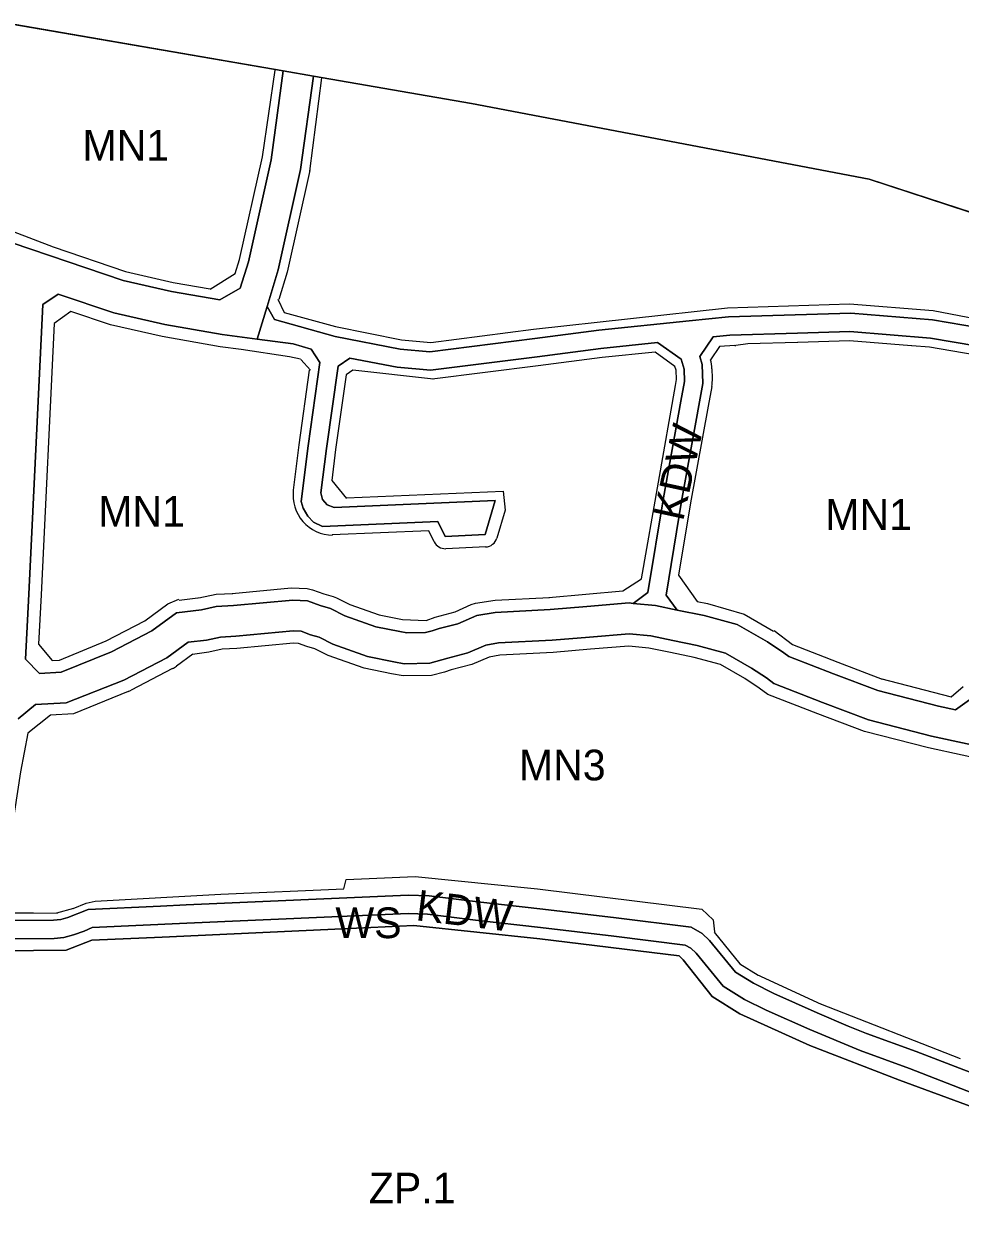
# Model space of a CAD drawing. Extents: x 7417187 to 7419415, y 5539178 to 5540826.
# Drawn here: x 7418734.7 to 7419039.6, y 5539846.6 to 5540233.3 of the extents above; entities that cross this region are included whole.
import ezdxf

# ---------------------------------------------------------------- set-up
doc = ezdxf.new("R2010")
doc.units = 0
for name, color, linetype in [('linie_rozgraniczajace', 7, 'Continuous'), ('linie_zabudowy_nieprzekraczalne', 7, 'Continuous'), ('oznaczenia_przeznaczen', 7, 'Continuous')]:
    doc.layers.add(name, color=color, linetype=linetype)

msp = doc.modelspace()

# ---------------------------------------------------------------- linework, layer by layer
at = {"layer": 'linie_rozgraniczajace'}
for p, q in [((7418819.13, 5540217.89), (7418625.49, 5540251.41)), ((7418828.99, 5540216.18), (7418819.13, 5540217.89)), ((7418880.47, 5540207.27), (7418828.99, 5540216.18)), ((7419009.97, 5540182.65), (7418880.47, 5540207.27)), ((7419099.77, 5540153.28), (7419009.97, 5540182.65))]:
    msp.add_line(p, q, dxfattribs=at)
for points in [[(7418625.49, 5540251.41), (7418819.13, 5540217.89), (7418815.24, 5540188.97), (7418807.81, 5540155.72), (7418805.17, 5540147.14), (7418798.55, 5540143.34), (7418782.74, 5540146.1), (7418766.98, 5540149.72), (7418730.85, 5540161.92)], [(7418730.85, 5540161.92), (7418766.98, 5540149.72), (7418782.74, 5540146.1), (7418798.55, 5540143.34), (7418805.17, 5540147.14), (7418807.81, 5540155.72), (7418815.24, 5540188.97), (7418819.13, 5540217.89), (7418828.99, 5540216.18), (7418824.79, 5540185.83), (7418817.49, 5540153.19), (7418813.9, 5540141.26), (7418810.67, 5540130.54), (7418799.23, 5540132.05), (7418780.56, 5540135.32), (7418763.99, 5540139.13), (7418745.86, 5540145.24), (7418740.88, 5540141.85), (7418736.32, 5540047.51), (7418735.2, 5540026.34), (7418739.81, 5540021.74), (7418746.89, 5540022.12), (7418763.27, 5540028.73), (7418776.34, 5540035.57), (7418784.38, 5540041.48), (7418792.57, 5540042.45), (7418797.34, 5540043.49), (7418802.95, 5540043.82), (7418822.24, 5540045.62), (7418827.02, 5540045.34), (7418831.18, 5540043.83), (7418834.51, 5540042.87), (7418839.23, 5540040.51), (7418849.31, 5540036.95), (7418857.16, 5540035.34), (7418859.4, 5540034.91), (7418865.52, 5540035.01), (7418867.7, 5540035.58), (7418869.96, 5540036.31), (7418875.98, 5540037.88), (7418882.23, 5540040.6), (7418888.22, 5540041.59), (7418906.07, 5540042.5), (7418918.05, 5540043.54), (7418931.85, 5540044.67), (7418933.06, 5540044.54), (7418940.38, 5540043.81), (7418947.41, 5540042.36), (7418956.2, 5540040.6), (7418967, 5540037.68), (7418976.9, 5540031.97), (7418982.23, 5540028.44), (7418983.78, 5540027.28), (7418998.3, 5540021.65), (7419012.74, 5540016.2), (7419032.57, 5540011.07), (7419038.11, 5540009.87), (7419044.21, 5540014.19)], [(7419045.91, 5540134.3), (7419030.57, 5540136.87), (7419004, 5540139.06), (7418964.15, 5540137.84), (7418951.36, 5540136.57), (7418921.88, 5540133.54), (7418901.06, 5540130.81), (7418866.87, 5540126.5), (7418857.22, 5540127.36), (7418836.04, 5540131.46), (7418816.26, 5540136.96), (7418813.9, 5540141.26), (7418817.49, 5540153.19), (7418824.79, 5540185.83), (7418828.99, 5540216.18), (7418880.47, 5540207.27), (7419009.97, 5540182.65), (7419099.77, 5540153.28)], [(7419044.7, 5540128.42), (7419029.99, 5540130.9), (7419003.67, 5540133.07), (7418986.59, 5540132.48), (7418964.64, 5540131.86), (7418959.2, 5540131.3), (7418954.85, 5540124.93), (7418955.58, 5540122.33), (7418955.83, 5540116.15), (7418948.87, 5540077.84), (7418943.82, 5540047.25), (7418947.41, 5540042.36), (7418940.38, 5540043.81), (7418933.06, 5540044.54), (7418937.87, 5540048.08), (7418942.96, 5540078.86), (7418948.64, 5540110.42), (7418949.85, 5540116.82), (7418949.73, 5540120.75), (7418948.74, 5540124.05), (7418941.06, 5540129.48), (7418922.62, 5540127.58), (7418901.82, 5540124.86), (7418867.16, 5540120.49), (7418856.23, 5540121.44), (7418840.8, 5540124.43), (7418837.01, 5540121.74), (7418833.26, 5540095.01), (7418831.42, 5540080.54), (7418831.98, 5540078.38), (7418833.44, 5540076.67), (7418835.74, 5540075.77), (7418888.21, 5540078.07), (7418884.9, 5540066.92), (7418871.91, 5540066.35), (7418869.5, 5540071.25), (7418831.98, 5540069.6), (7418829.04, 5540070.97), (7418827.12, 5540072.89), (7418825.64, 5540075.54), (7418825.01, 5540077.75), (7418827.31, 5540095.8), (7418831.09, 5540122.94), (7418828.2, 5540127.36), (7418822.37, 5540129), (7418810.67, 5540130.54), (7418813.9, 5540141.26), (7418816.26, 5540136.96), (7418836.04, 5540131.46), (7418857.22, 5540127.36), (7418866.87, 5540126.5), (7418901.06, 5540130.81), (7418921.88, 5540133.54), (7418951.36, 5540136.57), (7418964.15, 5540137.84), (7419004, 5540139.06), (7419030.57, 5540136.87), (7419045.91, 5540134.3)], [(7419044.21, 5540014.19), (7419038.11, 5540009.87), (7419032.57, 5540011.07), (7419012.74, 5540016.2), (7418998.3, 5540021.65), (7418983.78, 5540027.28), (7418982.23, 5540028.44), (7418976.9, 5540031.97), (7418967, 5540037.68), (7418956.2, 5540040.6), (7418947.41, 5540042.36), (7418943.82, 5540047.25), (7418948.87, 5540077.84), (7418955.83, 5540116.15), (7418955.58, 5540122.33), (7418954.85, 5540124.93), (7418959.2, 5540131.3), (7418964.64, 5540131.86), (7418986.59, 5540132.48), (7419003.67, 5540133.07), (7419029.99, 5540130.9), (7419044.7, 5540128.42)], [(7418732.84, 5540006.91), (7418738.47, 5540011.64), (7418748.5, 5540012.2), (7418767.2, 5540019.53), (7418781.24, 5540026.85), (7418788.18, 5540031.86), (7418794.22, 5540032.57), (7418798.71, 5540033.55), (7418803.71, 5540033.84), (7418822.41, 5540035.6), (7418824.98, 5540035.44), (7418828.08, 5540034.32), (7418830.86, 5540033.51), (7418835.31, 5540031.29), (7418846.63, 5540027.29), (7418855.22, 5540025.53), (7418858.53, 5540024.9), (7418866.88, 5540025.03), (7418872.77, 5540026.71), (7418879.26, 5540028.4), (7418885.09, 5540030.94), (7418889.29, 5540031.64), (7418906.75, 5540032.53), (7418918.88, 5540033.57), (7418931.76, 5540034.63), (7418938.87, 5540033.92), (7418946.03, 5540032.43), (7418953.92, 5540030.86), (7418963.13, 5540028.37), (7418971.63, 5540023.46), (7418976.48, 5540020.25), (7418978.9, 5540018.45), (7418994.73, 5540012.31), (7419009.71, 5540006.66), (7419030.26, 5540001.34), (7419051.98, 5539996.65)], [(7419051.98, 5539996.65), (7419030.26, 5540001.34), (7419009.71, 5540006.66), (7418994.73, 5540012.31), (7418978.9, 5540018.45), (7418976.48, 5540020.25), (7418971.63, 5540023.46), (7418963.13, 5540028.37), (7418953.92, 5540030.86), (7418946.03, 5540032.43), (7418938.87, 5540033.92), (7418931.76, 5540034.63), (7418918.88, 5540033.57), (7418906.75, 5540032.53), (7418889.29, 5540031.64), (7418885.09, 5540030.94), (7418879.26, 5540028.4), (7418872.77, 5540026.71), (7418866.88, 5540025.03), (7418858.53, 5540024.9), (7418855.22, 5540025.53), (7418846.63, 5540027.29), (7418835.31, 5540031.29), (7418830.86, 5540033.51), (7418828.08, 5540034.32), (7418824.98, 5540035.44), (7418822.41, 5540035.6), (7418803.71, 5540033.84), (7418798.71, 5540033.55), (7418794.22, 5540032.57), (7418788.18, 5540031.86), (7418781.24, 5540026.85), (7418767.2, 5540019.53), (7418748.5, 5540012.2), (7418738.47, 5540011.64), (7418732.84, 5540006.91)], [(7418727, 5539941.31), (7418744.32, 5539941.44), (7418746.69, 5539941.63), (7418749.03, 5539942.28), (7418755.67, 5539944.9), (7418779.15, 5539945.99), (7418787.51, 5539946.38), (7418859.85, 5539949.56), (7418866.64, 5539949.29), (7418882.5, 5539947.36), (7418903.67, 5539945), (7418927.54, 5539942.1), (7418952.02, 5539939.11), (7418955.53, 5539937.09), (7418958, 5539934.75), (7418966.41, 5539924.48), (7418972.29, 5539920.86), (7418978.94, 5539917.56), (7418993.08, 5539911.26), (7419003.13, 5539906.92), (7419009.15, 5539904.54), (7419025.25, 5539898.66), (7419057.16, 5539886.31)], [(7419057.16, 5539886.31), (7419025.25, 5539898.66), (7419009.15, 5539904.54), (7419003.13, 5539906.92), (7418993.08, 5539911.26), (7418978.94, 5539917.56), (7418972.29, 5539920.86), (7418966.41, 5539924.48), (7418958, 5539934.75), (7418955.53, 5539937.09), (7418952.02, 5539939.11), (7418927.54, 5539942.1), (7418903.67, 5539945), (7418882.5, 5539947.36), (7418866.64, 5539949.29), (7418859.85, 5539949.56), (7418787.51, 5539946.38), (7418779.15, 5539945.99), (7418755.67, 5539944.9), (7418749.03, 5539942.28), (7418746.69, 5539941.63), (7418744.32, 5539941.44), (7418727, 5539941.31)], [(7418725.92, 5539935.3), (7418744.58, 5539935.44), (7418747.74, 5539935.7), (7418750.89, 5539936.57), (7418754.28, 5539937.86), (7418756.98, 5539938.96), (7418787.78, 5539940.39), (7418859.87, 5539943.55), (7418866.16, 5539943.31), (7418881.8, 5539941.4), (7418902.97, 5539939.04), (7418926.82, 5539936.14), (7418950.08, 5539933.3), (7418951.92, 5539932.25), (7418953.59, 5539930.66), (7418962.4, 5539919.89), (7418969.38, 5539915.6), (7418976.38, 5539912.13), (7418990.67, 5539905.77), (7419007.01, 5539898.93), (7419023.14, 5539893.05), (7419054.07, 5539881.07)], [(7419054.07, 5539881.07), (7419023.14, 5539893.05), (7419007.01, 5539898.93), (7418990.67, 5539905.77), (7418976.38, 5539912.13), (7418969.38, 5539915.6), (7418962.4, 5539919.89), (7418953.59, 5539930.66), (7418951.92, 5539932.25), (7418950.08, 5539933.3), (7418926.82, 5539936.14), (7418902.97, 5539939.04), (7418881.8, 5539941.4), (7418866.16, 5539943.31), (7418859.87, 5539943.55), (7418787.78, 5539940.39), (7418756.98, 5539938.96), (7418754.28, 5539937.86), (7418750.89, 5539936.57), (7418747.74, 5539935.7), (7418744.58, 5539935.44), (7418725.92, 5539935.3)], [(7419043.74, 5539880.5), (7419019.82, 5539889.33), (7418990.65, 5539900.55), (7418967.84, 5539910.9), (7418958.82, 5539916.51), (7418949.36, 5539928.49), (7418948.05, 5539929.8), (7418902.71, 5539935.29), (7418861.65, 5539939.62), (7418838.4, 5539938.54), (7418779.73, 5539935.88), (7418756.83, 5539934.88), (7418748.43, 5539931.6), (7418705.75, 5539931.19)], [(7418705.75, 5539931.19), (7418748.43, 5539931.6), (7418756.83, 5539934.88), (7418779.73, 5539935.88), (7418838.4, 5539938.54), (7418861.65, 5539939.62), (7418902.71, 5539935.29), (7418948.05, 5539929.8), (7418949.36, 5539928.49), (7418958.82, 5539916.51), (7418967.84, 5539910.9), (7418990.65, 5539900.55), (7419019.82, 5539889.33), (7419043.74, 5539880.5), (7419059.22, 5539874.18), (7419059.44, 5539873.89), (7419061.66, 5539855.14), (7419063.63, 5539837.78)]]:
    msp.add_lwpolyline(points, dxfattribs=at)
msp.add_lwpolyline([(7418810.67, 5540130.54), (7418822.37, 5540129), (7418828.2, 5540127.36), (7418831.09, 5540122.94), (7418827.31, 5540095.8), (7418825.01, 5540077.75), (7418825.64, 5540075.54), (7418827.12, 5540072.89), (7418829.04, 5540070.97), (7418831.98, 5540069.6), (7418869.5, 5540071.25), (7418871.91, 5540066.35), (7418884.9, 5540066.92), (7418888.21, 5540078.07), (7418835.74, 5540075.77), (7418833.44, 5540076.67), (7418831.98, 5540078.38), (7418831.42, 5540080.54), (7418833.26, 5540095.01), (7418837.01, 5540121.74), (7418840.8, 5540124.43), (7418856.23, 5540121.44), (7418867.16, 5540120.49), (7418901.82, 5540124.86), (7418922.62, 5540127.58), (7418941.06, 5540129.48), (7418948.74, 5540124.05), (7418949.73, 5540120.75), (7418949.85, 5540116.82), (7418948.64, 5540110.42), (7418942.96, 5540078.86), (7418937.87, 5540048.08), (7418933.06, 5540044.54), (7418931.85, 5540044.67), (7418918.05, 5540043.54), (7418906.07, 5540042.5), (7418888.22, 5540041.59), (7418882.23, 5540040.6), (7418875.98, 5540037.88), (7418869.96, 5540036.31), (7418867.7, 5540035.58), (7418865.52, 5540035.01), (7418859.4, 5540034.91), (7418857.16, 5540035.34), (7418849.31, 5540036.95), (7418839.23, 5540040.51), (7418834.51, 5540042.87), (7418831.18, 5540043.83), (7418827.02, 5540045.34), (7418822.24, 5540045.62), (7418802.95, 5540043.82), (7418797.34, 5540043.49), (7418792.57, 5540042.45), (7418784.38, 5540041.48), (7418776.34, 5540035.57), (7418763.27, 5540028.73), (7418746.89, 5540022.12), (7418739.81, 5540021.74), (7418735.2, 5540026.34), (7418736.32, 5540047.51), (7418740.88, 5540141.85), (7418745.86, 5540145.24), (7418763.99, 5540139.13), (7418780.56, 5540135.32), (7418799.23, 5540132.05)], close=True, dxfattribs=at)
at = {"layer": 'linie_zabudowy_nieprzekraczalne'}
for p, q in [((7418986.69, 5540129.48), (7418986.65, 5540129.48)), ((7419023.82, 5540128.35), (7419023.76, 5540128.35)), ((7418902.22, 5540121.89), (7418902.2, 5540121.89))]:
    msp.add_line(p, q, dxfattribs=at)
for points in [[(7418812.38, 5540189.91), (7418816.5, 5540218.21)], [(7418831.66, 5540215.63), (7418827.66, 5540185.25)], [(7418803.54, 5540151.92), (7418804.91, 5540156.49), (7418812.38, 5540189.91)], [(7418827.78, 5540185.47), (7418820.4, 5540152.43), (7418817.71, 5540143.49)], [(7418724.54, 5540168.08), (7418744.19, 5540160.59), (7418767.8, 5540152.62), (7418783.34, 5540149.05), (7418795.33, 5540146.96)], [(7418795.34, 5540146.88), (7418803.54, 5540151.92)], [(7418817.4, 5540143.58), (7418819.5, 5540139.23)], [(7418900.67, 5540133.79), (7418963.86, 5540140.82), (7419003.54, 5540142.07), (7419030.8, 5540139.86), (7419053.93, 5540135.47)], [(7418750.02, 5540139.62), (7418744.54, 5540135.69)], [(7418805.47, 5540127.19), (7418798.63, 5540128.1), (7418779.77, 5540131.4), (7418762.9, 5540135.27), (7418750.02, 5540139.62)], [(7418819.5, 5540139.23), (7418836.21, 5540134.65)], [(7418744.54, 5540135.69), (7418740.32, 5540047.31), (7418739.47, 5540031.22)], [(7418836.21, 5540134.65), (7418857.66, 5540130.33), (7418867.24, 5540129.48)], [(7418867.24, 5540129.48), (7418900.67, 5540133.79)], [(7418986.65, 5540129.48), (7418970.46, 5540129.04), (7418966.5, 5540128.5)], [(7419023.76, 5540128.35), (7419003.59, 5540130.06), (7418986.69, 5540129.48)], [(7418821.2, 5540124.84), (7418805.47, 5540127.19)], [(7418940.31, 5540126.39), (7418922.97, 5540124.6), (7418902.22, 5540121.89)], [(7418946.88, 5540115.49), (7418947.2, 5540117.44), (7418947.1, 5540120.53), (7418946.72, 5540121.64), (7418940.31, 5540126.39)], [(7418961.22, 5540128.16), (7418958.29, 5540123.86)], [(7418966.21, 5540128.47), (7418961.22, 5540128.16)], [(7419049.6, 5540124.28), (7419044.13, 5540125.48), (7419029.63, 5540127.92), (7419023.82, 5540128.35)], [(7418824.76, 5540124.04), (7418821.2, 5540124.84)], [(7418828.07, 5540120.46), (7418824.84, 5540123.96)], [(7418902.2, 5540121.89), (7418867.68, 5540117.53)], [(7418822.45, 5540081.4), (7418824.34, 5540096.21), (7418827.75, 5540120.51)], [(7418839.65, 5540118.96), (7418836.23, 5540094.61), (7418834.96, 5540084.56)], [(7418841.84, 5540120.5), (7418839.65, 5540118.96)], [(7418868.11, 5540117.58), (7418841.82, 5540120.52)], [(7418958.77, 5540120.96), (7418958.89, 5540117.87)], [(7418935.78, 5540052.52), (7418946.88, 5540115.49)], [(7418958.69, 5540115.16), (7418957.5, 5540108.8), (7418951.83, 5540077.33), (7418947.92, 5540053.68)], [(7418834.96, 5540084.56), (7418839.8, 5540078.7)], [(7418839.8, 5540078.96), (7418890.77, 5540081.13)], [(7418890.77, 5540081.13), (7418891.44, 5540074.87)], [(7418891.44, 5540074.87), (7418888.73, 5540065.78)], [(7418866.57, 5540068.15), (7418835.09, 5540066.91)], [(7418868.33, 5540064.58), (7418866.57, 5540068.15)], [(7418885.08, 5540062.92), (7418872.09, 5540062.35)], [(7418929.72, 5540048.6), (7418935.78, 5540052.52)], [(7418947.92, 5540053.68), (7418953.93, 5540045.15)], [(7418797.27, 5540047.5), (7418802.76, 5540047.81)], [(7418802.55, 5540047.8), (7418821.71, 5540049.59)], [(7418821.71, 5540049.59), (7418826.97, 5540049.35)], [(7418826.97, 5540049.35), (7418828.67, 5540049)], [(7418828.67, 5540049), (7418832.42, 5540047.64)], [(7418917.73, 5540047.53), (7418929.72, 5540048.6)], [(7418743.96, 5540025.96), (7418746.33, 5540026.09), (7418761.5, 5540032.32), (7418774.1, 5540038.89), (7418781.58, 5540044.39), (7418785.19, 5540045.93)], [(7418785.23, 5540045.61), (7418792.2, 5540046.43)], [(7418791.62, 5540046.34), (7418797.27, 5540047.5)], [(7418832.42, 5540047.64), (7418835.45, 5540046.76)], [(7418835.45, 5540046.76), (7418836.47, 5540046.37)], [(7418836.47, 5540046.37), (7418840.8, 5540044.2)], [(7418840.8, 5540044.2), (7418850.38, 5540040.81)], [(7418875.13, 5540041.79), (7418880.4, 5540044.17)], [(7418880.4, 5540044.17), (7418881.82, 5540044.59)], [(7418881.82, 5540044.59), (7418888.13, 5540045.6)], [(7418888.13, 5540045.6), (7418905.9, 5540046.5)], [(7418905.69, 5540046.49), (7418917.7, 5540047.52)], [(7418953.93, 5540045.15), (7418957.32, 5540044.45)], [(7418957.32, 5540044.45), (7418969.23, 5540041.01)], [(7418850.38, 5540040.81), (7418857.98, 5540039.26)], [(7418865.7, 5540039.01), (7418868.67, 5540040.1)], [(7418868.67, 5540040.1), (7418875.13, 5540041.79)], [(7418969.23, 5540041.01), (7418978.85, 5540035.46)], [(7418857.98, 5540039.26), (7418865.7, 5540039.01)], [(7418979.01, 5540035.75), (7418984.98, 5540031.11)], [(7418739.47, 5540031.22), (7418743.96, 5540025.96)], [(7419051.27, 5539992.72), (7419029.34, 5539997.45), (7419008.5, 5540002.84), (7418993.3, 5540008.57), (7418976.95, 5540014.92), (7418974.18, 5540016.98), (7418969.53, 5540020.06), (7418961.59, 5540024.64), (7418953.01, 5540026.97), (7418945.23, 5540028.51), (7418938.26, 5540029.96), (7418931.72, 5540030.61), (7418919.22, 5540029.59), (7418907.03, 5540028.54), (7418889.73, 5540027.66), (7418886.23, 5540027.07), (7418880.57, 5540024.61), (7418873.89, 5540022.87), (7418871.63, 5540022.14), (7418867.43, 5540021.04), (7418858.18, 5540020.9), (7418854.45, 5540021.61), (7418845.55, 5540023.43), (7418833.75, 5540027.6), (7418829.4, 5540029.77), (7418826.84, 5540030.51), (7418824.16, 5540031.49), (7418822.48, 5540031.59), (7418804.01, 5540029.86), (7418799.26, 5540029.58), (7418794.89, 5540028.63), (7418789.58, 5540027.87)], [(7418984.98, 5540031.11), (7418999.76, 5540025.37)], [(7418789.77, 5540027.98), (7418784.37, 5540024.1)], [(7418999.71, 5540025.39), (7419014.25, 5540019.91)], [(7418783.1, 5540023.31), (7418769.59, 5540016.24)], [(7419013.64, 5540020.11), (7419036.62, 5540014.15)], [(7419036.62, 5540014.15), (7419040.61, 5540017.43)], [(7418768.7, 5540015.83), (7418750.85, 5540008.62)], [(7418743.35, 5540008.12), (7418736.01, 5540002.32)], [(7418750.85, 5540008.62), (7418743.35, 5540008.12)], [(7418736.01, 5540002.32), (7418733.55, 5539989.74), (7418730.7, 5539970.46)], [(7418839.63, 5539954.61), (7418862.09, 5539955.66), (7418902.01, 5539951.59), (7418955.49, 5539945.01), (7418959.21, 5539941.49)], [(7418798.88, 5539949.89), (7418838.84, 5539951.58)], [(7418838.84, 5539951.58), (7418839.63, 5539954.61)], [(7418754.97, 5539946.93), (7418757.91, 5539947.6)], [(7418757.91, 5539947.6), (7418798.83, 5539949.88)], [(7418729.89, 5539943.79), (7418737.7, 5539943.79)], [(7418737.78, 5539943.79), (7418745.62, 5539943.7)], [(7418745.47, 5539943.77), (7418750.96, 5539945.26)], [(7418750.7, 5539945.16), (7418754.97, 5539946.93)], [(7418959.21, 5539941.49), (7418959.57, 5539937.59)], [(7418959.49, 5539937.48), (7418967.84, 5539927.12)], [(7418967.84, 5539927.12), (7418973.85, 5539923.43)], [(7418973.43, 5539923.65), (7418994.31, 5539914)], [(7418994.09, 5539914.1), (7419039.61, 5539896.33)]]:
    msp.add_lwpolyline(points, dxfattribs=at)
for centre, radius, start, end in [((7418966.11, 5540130.85), 2.38, 272.3971, 279.4152), ((7418946.79, 5540120.47), 11.99, 2.3568, 16.4397), ((7418947.35, 5540117.36), 11.56, 349.0271, 2.5313), ((7418835.34, 5540079.76), 13, 172.7289, 269.5098), ((7418871.93, 5540066.37), 4.02, 206.4133, 272.2436), ((7418884.88, 5540066.93), 4.01, 272.8047, 343.357), ((7418778.68, 5540031.84), 9.61, 297.419, 306.3482), ((7418765.95, 5540022.96), 7.64, 291.0598, 298.4088)]:
    msp.add_arc(centre, radius, start, end, dxfattribs=at)

# ---------------------------------------------------------------- texts
at = {"layer": 'oznaczenia_przeznaczen'}
for s, p in [('MN1', (7418753.77, 5540188.7)), ('MN1', (7418758.9, 5540069.52)), ('MN1', (7418995.67, 5540068.48)), ('MN3', (7418895.91, 5539986.91)), ('WS', (7418836.15, 5539935.53)), ('ZP.1', (7418847.02, 5539849.15))]:
    msp.add_text(s, height=10, dxfattribs=at).set_placement(p)
for rotation, p in [(77.7562, (7418949.34, 5540071)), (353.0607, (7418862.06, 5539941.4))]:
    msp.add_text('KDW', height=10, rotation=rotation, dxfattribs=at).set_placement(p)

doc.saveas('drawing.dxf')
